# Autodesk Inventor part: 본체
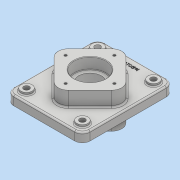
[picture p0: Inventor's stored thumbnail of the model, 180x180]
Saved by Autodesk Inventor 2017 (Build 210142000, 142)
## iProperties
Part Number: 본체
Material: 일반
Document SubType Name: Modeling
Designer: MRC
Density: 1 g/cm^3
Appearance: 기본값
Author: MRC
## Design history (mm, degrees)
sketch "스케치1"
  geometry: L1 (75, -90)-(-75, -90); L2 (-75, -90)-(-75, 90); L3 (-75, 90)-(75, 90); L4 (75, 90)-(75, -90); L5 (75, -90)-(-75, 90); L6 (-75, -90)-(75, 90); 1 further point
  constraints: 12 end point, 2 midpoint, 2 parallel, 1 horizontal, 1 perpendicular
  dimensions: "d0" = 150 distance of L2.end L3.end; "d1" = 180 distance of L1.end L2.end
extrude "돌출1" new body sketch "스케치1" distance "d2" = 18; taper "d3" = 0 deg
fillet "모깎기1" dims "d4" = 15
sketch "스케치2"
  geometry: L1 (0, 70.711)-(70.711, 0); L2 (70.711, 0)-(0, -70.711); L3 (0, -70.711)-(-70.711, 0); L4 (-70.711, 0)-(0, 70.711); 2 further points
  constraints: 8 end point, 1 coincident, 1 vertical alignment, 9 other
  dimensions: "d5" = 100 distance between parallel lines of L2 L4
extrude "돌출2" join sketch "스케치2" distance "d6" = 29; taper "d8" = 0 deg; dims "d7" = 41, "d9" = 0
fillet "모깎기2" dims "d10" = 20
sketch "스케치3"
  geometry: 2 further points
  constraints: 1 coincident
hole "구멍1" sketch "스케치3" at (0, 0) diameter "d11" = 45; stored, may be unused: countersink angle "d15" = 90 deg, drill point angle "d17" = 118 deg; dims "d12" = 6, "d13" = 62, "d14" = 22, "d16" = 8
sketch "스케치4"
  geometry: C1 r 31 at (0, 0); 1 further point
  constraints: 1 centre point, 1 coincident
  dimensions: "d18" = 62 diameter of C1
extrude "돌출3" cut sketch "스케치4" distance "d19" = 22; taper "d20" = 0 deg
sketch "스케치5"
  geometry: 2 further points
  constraints: 1 vertical alignment
  dimensions: "d21" = 48 distance of point (0, 48) point (0, 0)
hole "구멍2" sketch "스케치5" at (0, 48) diameter "d22" = 4.917; stored, may be unused: countersink angle "d26" = 90 deg, drill point angle "d28" = 118 deg; dims "d23" = 10, "d24" = 62, "d25" = 22, "d27" = 13
node "작업 평면1"
sketch "스케치6"
  geometry: C1 r 11 at (55, 70); 1 further point
  constraints: 1 centre point
  dimensions: "d32" = 22 diameter of C1; "d46" = 55 horizontal distance of C1.centre point (0, 0); "d47" = 70 vertical distance of point (0, 0) C1.centre
extrude "돌출4" join sketch "스케치6" distance "d33" = 5; taper "d34" = 0 deg
sketch "스케치7"
  geometry: C1 r 5.5 at (0, 0); C2 r 11 at (0, 0) reference; 1 further point
  constraints: 1 centre point, 1 concentric
  dimensions: "d35" = 11 diameter of C1
extrude "돌출5" cut sketch "스케치7" stored distance "d36" = 5; taper "d37" = 0 deg
sketch "스케치8"
  geometry: L1 (60, 90)-(-60, 90) reference; 2 further points
  constraints: 1 vertical alignment, 1 other
  dimensions: "d38" = 15 distance from line of point (0, 75) L1
feature "엠보싱1" sketch "스케치8" dims "d0" = 150, "d1" = 180, "d10" = 20, "d39" = 0.5, "d40" = 0
fillet "모깎기3" dims "d41" = 3
fillet "모깎기4" dims "d42" = 1
chamfer "모따기1" distance "d43" = 1; stored, may be unused: second distance "d44" = 2, angle "d45" = 45 deg
fillet "모깎기5" dims "d48" = 2
node "솔리드1"
pattern_circular "원형 패턴1" dims angle "d30" = 360 deg
mirror "미러1"
mirror "미러2"
mirror "미러3"
